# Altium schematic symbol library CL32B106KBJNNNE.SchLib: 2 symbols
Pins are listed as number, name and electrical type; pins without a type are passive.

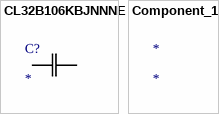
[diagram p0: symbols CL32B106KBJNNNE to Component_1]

## CL32B106KBJNNNE
designator C?
No Description Available; Mfr_Name: Samsung
footprint CAP_CL32_SAM
pins: 1, 2

## Component_1
designator *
